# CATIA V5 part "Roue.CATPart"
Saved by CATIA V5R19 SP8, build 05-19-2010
Part number: Roue
Bounding box of the stored display mesh (mm): x -9.5 to 9.5, y -9.484 to 9.484, z -1.5 to 5.5
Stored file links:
  D:\Travail\1 - ITEC_Turgot\00 - TP en cours de préparration\TP 4-9.2d Imprim3D_Uprint\Diviseur\Roue.CATPart
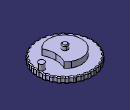
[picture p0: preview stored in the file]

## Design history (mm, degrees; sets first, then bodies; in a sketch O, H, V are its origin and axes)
Body1 (main body)
  Sketch1 on yz-plane, origin (0, 0, 0), H (0, 1, 0), V (0, 0, 1)
    point P1 (0, 5.5)
    line L1 (0, 5.5) -> (-1, 5.5)
    line L2 (-1, 5.5) -> (-1, 4)
    line L3 (-1, 4) -> (-5.67, 4)
    line L4 (-5.67, 4) -> (-5.67, 2)
    line L5 (-5.67, 2) -> (-9.5, 2)
    line L6 (-9.5, 2) -> (-9.5, 0)
    line L7 (-9.5, 0) -> (-1, 0)
    point P8 (-1, 0)
    line L8 (-1, 0) -> (-1, -1.5)
    line L9 (-1, -1.5) -> (0, -1.5)
    point P10 (0, -1.5)
    axis line L10 (0, 22.432) -> (0, -19.0241)
    point P11 (0, 22.432)
    "Radius" L2 L10 = 1
    distance L1 L3 = 1.5
    "Radius" L4 L10 = 5.67
    distance L3 L5 = 2
    "Radius" L6 L10 = 9.5
    distance L5 L7 = 2
    distance L9 L7 = 1.5
    horizontal: L1 H, L3 H, L5 H, L7 H, L9 H
    vertical: L2 V, L4 V
    parallelism: L6 L4, L8 L2
    coincidence: P8 L2, P10 V, P11 V, P1 L10, L7 H
  Shaft1: profile Sketch1, axis Sketch1.L10, angle 360
  Chamfer1: length 0.3, angle 45, on edge [face of Shaft1 from Sketch1.L1 | face of Shaft1 from Sketch1.L2]; edge [face of Shaft1 from Sketch1.L8 | face of Shaft1 from Sketch1.L9]
  Sketch2 on face of Shaft1 from Sketch1.L5, origin (0, 0, 2), H (1, 0, 0), V (0, 1, 0)
    circle A1 centre (11.5, 0) radius 8.3
    point P1 (11.5, 0)
    reference projected point E1 (0, 0) from axis of face of Shaft1 from Sketch1.L2
    reference intersected line E2 through (0, 0) direction (-1, 0) from zx-plane
    radius A1 = 8.3
    distance E1 P1 = 11.5
    coincidence: P1 E2
  Pocket1: profile Sketch2, direction (0, 0, 1), length 20
  Sketch3 on face of Pocket1, origin (0, 0, 2), H (1, 0, 0), V (0, 1, 0)
    circle A1 centre (8.132, 0) radius 1
    point P1 (8.132, 0)
    reference intersected line E1 through (0, 0) direction (-1, 0) from zx-plane
    reference projected point E2 (0, 0) from axis of face of Shaft1 from Sketch1.L2
    radius A1 = 1
    distance P1 E2 = 8.132
    coincidence: P1 E1
  Pad1: profile Sketch3, direction (0, 0, 1), up to face of Shaft1 from Sketch1.L3
  Sketch4 on face of Pocket1, origin (0, 0, 2), H (1, 0, 0), V (0, 1, 0)
    circle A1 centre (0, 9.875) radius 0.675
    point P1 (0, 9.875)
    reference projected circle E1 centre (0, 0) radius 9.5 from edge [face of Shaft1 from Sketch1.L6 | face of Shaft1 from Sketch1.L7]
    reference intersected line E2 through (0, 0) direction (0, 1) from yz-plane
    radius A1 = 0.675
    distance A1 E1 = 0.3
    coincidence: P1 E2
  Pocket2: profile Sketch4, direction (0, 0, -1), through (limit type 3)
  Fillet1: radius 0.3, on edge [face of Shaft1 from Sketch1.L7 | face of Pocket2 from Sketch4.A1]; edge [face of Pocket1 | face of Pocket2 from Sketch4.A1]
  CircPattern1: of Pocket2, Fillet1, instances 30, angular step 12 {= 360.0*1 deg/CircPattern1.AngularNumber}, axis from face of Shaft1 from Sketch1.L4
  Fillet2: radius 0.3, on edge [face of Shaft1 from Sketch1.L6 | face of Shaft1 from Sketch1.L7] (x30); edge [face of Pocket1 | face of Shaft1 from Sketch1.L6] (x30)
